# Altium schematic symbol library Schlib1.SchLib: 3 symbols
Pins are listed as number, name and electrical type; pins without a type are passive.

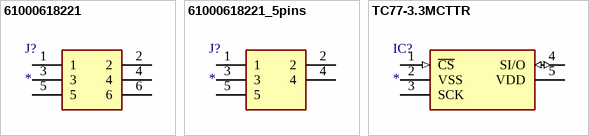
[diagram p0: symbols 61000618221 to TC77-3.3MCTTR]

## 61000618221
designator J?
Connector; Manufacturer_Name: Wurth Elektronik; Manufacturer_Part_Number: 61000618221
footprint 61000618221
pins: 1, 2, 3, 4, 5, 6

## 61000618221_5pins
designator J?
Connector; Manufacturer_Name: Wurth Elektronik; Manufacturer_Part_Number: 61000618221
footprint 61000618221_5pins
pins: 1, 2, 3, 4, 5

## TC77-3.3MCTTR
designator IC?
Integrated Circuit; Manufacturer_Name: Microchip; Manufacturer_Part_Number: TC77-3.3MCTTR
footprint SOT95P280X145-5N
pins: 1 ~{CS} (in), 2 VSS (power), 3 SCK, 4 SI/O (io), 5 VDD (power)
